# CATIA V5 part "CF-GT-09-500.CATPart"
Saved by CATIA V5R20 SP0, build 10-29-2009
Part number: CF-GT-09-500
Definition: NONE
Nomenclature: CF-GT-09-500
Source: Unknown
Description: CF-GT-09-500
Bounding box of the stored display mesh (mm): x 0 to 500, y 0 to 19, z -12 to 12
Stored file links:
  C:\Users\Utente\Desktop\IO LAVORO\3D X SITO CF\X SITO\PLASTICA\CF-GT\CF-GT-09-500.CATPart
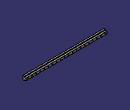
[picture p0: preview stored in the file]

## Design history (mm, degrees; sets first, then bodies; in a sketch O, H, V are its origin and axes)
Body1 "CF-GT-09-500" (main body)
  Solid1: solid without history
